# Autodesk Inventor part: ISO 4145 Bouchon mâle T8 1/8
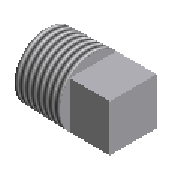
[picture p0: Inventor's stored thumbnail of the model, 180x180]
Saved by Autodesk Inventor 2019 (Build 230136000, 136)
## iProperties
Created: 2018-01
Part Number: ISO 4145 Bouchon mâle T8 1/8
Material: Acier, non allié
Description: ISO 4145 Raccords en acier non allié taraudés conformément à ISO 7/1 - Bouchon mâle T8
Document SubType Name: Modeling
Standard: ISO 4145
Designer: Thier
Standard Revision: Second edition 1986-07-15
Standards Organization: ISO
Language: fr-FR
Size Designation: 1/8
Categories: <MemberInstance><Categories><Category DisplayName="Tubes et tuyaux" InternalName="4347fa0f-2144-441d-94cd-e3e15c92b736" Mnemonic="TUBEANDPIPE"><CategoryParamete
Density: 1 g/cm^3
Appearance: Acier
NAME: PIPING: ISO 4145 Plug T8
DATA: <meta><inlinegroups number="0" deflen="0"></inlinegroups><connections number="1"></connections><angles></angles></meta>
IsCustomPart: 0
Author: Thier
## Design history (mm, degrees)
sketch "Sketch1"
  geometry: L1 (0, 0)-(-7, 0); L2 (0, 4.74)-(0, 0); L3 (0, 4.74)-(-7, 4.959); L4 (-7, 4.959)-(-7, 0); L5 (-3.97, 4.864)-(-3.97, 0)
  constraints: 10 end point, 2 point on line, 1 horizontal, 1 perpendicular, 1 vertical
  dimensions: "d0" = 7 distance between parallel lines of L2 L4 (= L - n); "d1" = 1.78991 deg angle of L1 L3; "d12" = 3.97 distance between parallel lines of L2 L5 (= a); "d13" = 9.728 diameter of L5.start L1 (= MjD)
revolve "Revolve1" sketch "Sketch1" stored, may be unused: angle "d4" = 90 deg
sketch "Sketch2"
  geometry: C1 r 4.74 at (0, 0) reference; C2 r 4.3 at (0, 0)
  constraints: 1 centre point, 1 coincident, 1 concentric
  dimensions: "d2" = 8.6 diameter of C2 (= d3)
extrude "Extrude1" cut sketch "Sketch2" distance "d5" = 6 (= -n + L - k); taper "d6" = 0 deg
sketch "Sketch3"
  geometry: L1 (-3.5, -3.5)-(3.5, -3.5); L2 (3.5, -3.5)-(3.5, 3.5); L3 (3.5, 3.5)-(-3.5, 3.5); L4 (-3.5, 3.5)-(-3.5, -3.5); L5 (-3.5, -3.5)-(3.5, 3.5); L6 (3.5, -3.5)-(-3.5, 3.5); C1 r 4.959 at (0, 0) reference; 1 further point
  constraints: 12 end point, 2 parallel, 2 perpendicular, 1 coincident, 1 horizontal, 1 midpoint
  dimensions: "d7" = 7 distance of L2.end L3.end (= S1)
extrude "Extrude2" join sketch "Sketch3" distance "d10" = 6 (= n); taper "d11" = 0 deg
workaxis "Work Axis1"
workpoint "Work Point1"
workaxis "Work Axis2"
workpoint "Work Point2"
body "Solid1"
feature "Filetage1" dims "d8" = 10, "d9" = 0
other parameters: "L" = 13 [user parameter; used in 2 equation terms], "n" = 6 [user parameter; used in 3 equation terms], "d3" = 8.6 [user parameter; used in 1 equation term], "k" = 1 [user parameter; used in 1 equation term], "S1" = 7 [user parameter; used in 1 equation term], "a" = 3.97 [user parameter; used in 1 equation term], "MjD" = 9.728 [user parameter; used in 1 equation term], "a1" = 2.5 [user parameter], "Size_Designation" = 1.25 [user parameter]
